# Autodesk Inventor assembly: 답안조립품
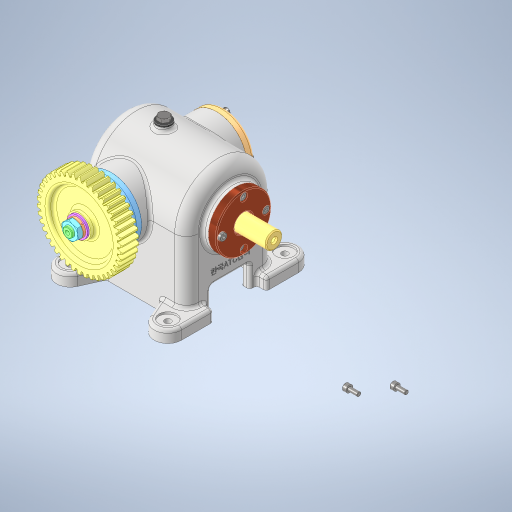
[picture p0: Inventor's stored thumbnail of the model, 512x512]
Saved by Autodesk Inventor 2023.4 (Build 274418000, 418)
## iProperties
Created: 2024-09
Part Number: 답안조립품
Document SubType Name: Assembly
Designer: EDU
Author: EDU
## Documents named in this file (17)
- C:\Users\EDU\Desktop\740904V1022\답안조립품.iam
- C:\Users\EDU\Desktop\740904V1022\본체.ipt
- C:\Users\EDU\Desktop\740904V1022\깊은 홈 볼베어링 6203\깊은 홈 볼베어링 6203.ipt
- C:\Users\EDU\Desktop\740904V1022\뒷커버\뒷커버.ipt
- C:\Users\EDU\Desktop\740904V1022\앞커버\앞커버.ipt
- C:\Users\EDU\Desktop\740904V1022\편심축\편심축.ipt
- C:\Users\EDU\Desktop\740904V1022\오일실 17 32 8\오일실 17 32 8.ipt
- C:\Users\EDU\Desktop\740904V1022\스프링와셔 M10\스프링와셔 M10.ipt
- C:\Users\EDU\Desktop\740904V1022\평와셔 M10\평와셔 M10.ipt
- C:\Users\EDU\Desktop\740904V1022\스퍼 기어\스퍼 기어.ipt
- C:\Users\EDU\Desktop\740904V1022\평행키 3x3x14\평행키 3x3x14.ipt
- C:\Users\EDU\Desktop\740904V1022\로드\로드.ipt
- C:\Users\EDU\Desktop\740904V1022\부시\부시.ipt
- C:\Users\EDU\Desktop\740904V1022\육각 너트 M10x1\육각 너트 M10x1.ipt
- C:\Users\EDU\Desktop\740904V1022\실링 패드\실링 패드.ipt
- C:\Users\EDU\Desktop\740904V1022\육각 머리 볼트 M6x0.75x12\육각 머리 볼트 M6x0.75x12.ipt
- C:\Users\EDU\Desktop\740904V1022\육각 소켓 머리 볼트 M4x10\육각 소켓 머리 볼트 M4x10.ipt
